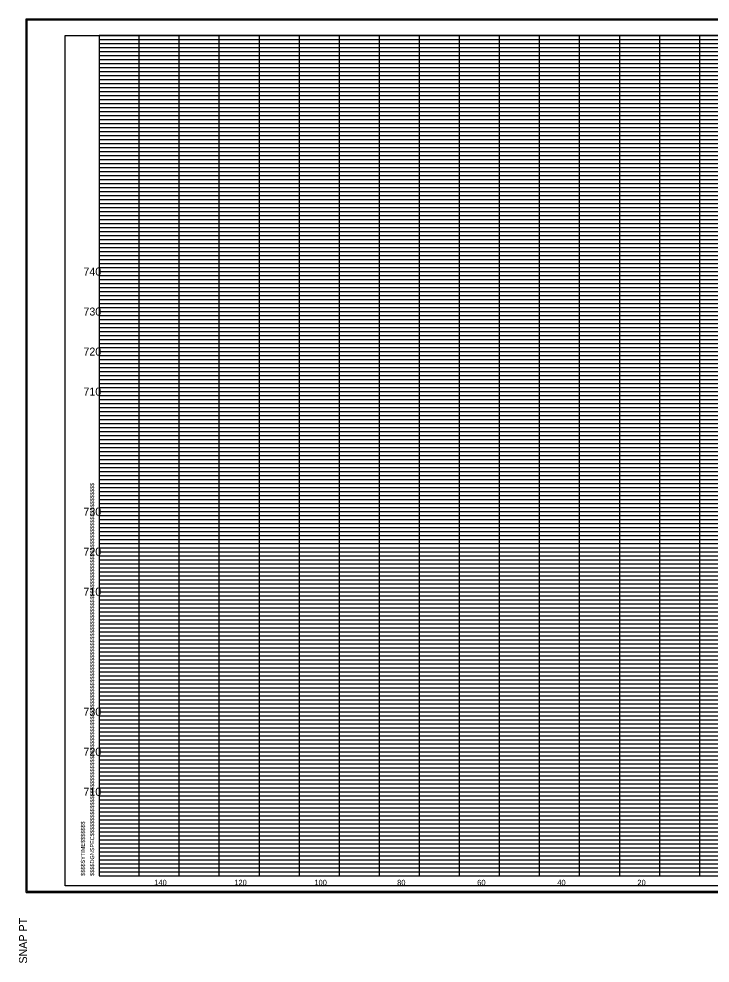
# Model space of a CAD drawing. Extents: x -200 to 1704, y -325 to 2307.
# Drawn here: x 979.9 to 1152.6, y 1248.2 to 1484.1 of the extents above; entities that cross this region are included whole.
import ezdxf

# ---------------------------------------------------------------- set-up
doc = ezdxf.new("R2010")
doc.units = 0
for name, color, linetype in [('DESIGN - SHEET - Corner Text', 7, 'Continuous'), ('DESIGN - SHEET - Light Grid', 7, 'Continuous'), ('DESIGN - SHEET - Linework', 7, 'Continuous'), ('DESIGN - SHEET - Plot Shape', 7, 'Continuous'), ('DESIGN - TYPICAL - Text', 7, 'Continuous')]:
    doc.layers.add(name, color=color, linetype=linetype)

msp = doc.modelspace()

# ---------------------------------------------------------------- linework, layer by layer
at = {"layer": 'DESIGN - SHEET - Light Grid'}
for p, q in [((1000, 1479), (1080, 1479)), ((1000, 1478), (1080, 1478)), ((1080, 1479), (1160, 1479)), ((1080, 1478), (1160, 1478)), ((1000, 1477), (1080, 1477)), ((1000, 1476), (1080, 1476)), ((1000, 1475), (1080, 1475)), ((1080, 1477), (1160, 1477)), ((1080, 1476), (1160, 1476)), ((1080, 1475), (1160, 1475)), ((1000, 1474), (1080, 1474)), ((1000, 1473), (1080, 1473)), ((1080, 1474), (1160, 1474)), ((1080, 1473), (1160, 1473)), ((1000, 1472), (1080, 1472)), ((1000, 1471), (1080, 1471)), ((1080, 1472), (1160, 1472)), ((1080, 1471), (1160, 1471)), ((1000, 1469), (1080, 1469)), ((1000, 1468), (1080, 1468)), ((1080, 1469), (1160, 1469)), ((1080, 1468), (1160, 1468)), ((1000, 1467), (1080, 1467)), ((1000, 1466), (1080, 1466)), ((1080, 1467), (1160, 1467)), ((1080, 1466), (1160, 1466)), ((1000, 1465), (1080, 1465)), ((1000, 1464), (1080, 1464)), ((1000, 1463), (1080, 1463)), ((1080, 1465), (1160, 1465)), ((1080, 1464), (1160, 1464)), ((1080, 1463), (1160, 1463)), ((1000, 1462), (1080, 1462)), ((1000, 1461), (1080, 1461)), ((1080, 1462), (1160, 1462)), ((1080, 1461), (1160, 1461)), ((1000, 1459), (1080, 1459)), ((1080, 1459), (1160, 1459)), ((1000, 1458), (1080, 1458)), ((1000, 1457), (1080, 1457)), ((1000, 1456), (1080, 1456)), ((1080, 1458), (1160, 1458)), ((1080, 1457), (1160, 1457)), ((1080, 1456), (1160, 1456)), ((1000, 1455), (1080, 1455)), ((1000, 1454), (1080, 1454)), ((1080, 1455), (1160, 1455)), ((1080, 1454), (1160, 1454)), ((1000, 1453), (1080, 1453)), ((1000, 1452), (1080, 1452)), ((1080, 1453), (1160, 1453)), ((1080, 1452), (1160, 1452)), ((1000, 1451), (1080, 1451)), ((1000, 1449), (1080, 1449)), ((1080, 1451), (1160, 1451)), ((1080, 1449), (1160, 1449)), ((1000, 1448), (1080, 1448)), ((1000, 1447), (1080, 1447)), ((1080, 1448), (1160, 1448)), ((1080, 1447), (1160, 1447)), ((1000, 1446), (1080, 1446)), ((1000, 1445), (1080, 1445)), ((1080, 1446), (1160, 1446)), ((1080, 1445), (1160, 1445)), ((1000, 1444), (1080, 1444)), ((1000, 1443), (1080, 1443)), ((1000, 1442), (1080, 1442)), ((1080, 1444), (1160, 1444)), ((1080, 1443), (1160, 1443)), ((1080, 1442), (1160, 1442)), ((1000, 1441), (1080, 1441)), ((1080, 1441), (1160, 1441)), ((1000, 1439), (1080, 1439)), ((1000, 1438), (1080, 1438)), ((1000, 1437), (1080, 1437)), ((1080, 1439), (1160, 1439)), ((1080, 1438), (1160, 1438)), ((1080, 1437), (1160, 1437)), ((1000, 1436), (1080, 1436)), ((1000, 1435), (1080, 1435)), ((1080, 1436), (1160, 1436)), ((1080, 1435), (1160, 1435)), ((1000, 1434), (1080, 1434)), ((1000, 1433), (1080, 1433)), ((1080, 1434), (1160, 1434)), ((1080, 1433), (1160, 1433)), ((1000, 1432), (1080, 1432)), ((1000, 1431), (1080, 1431)), ((1080, 1432), (1160, 1432)), ((1080, 1431), (1160, 1431)), ((1000, 1429), (1080, 1429)), ((1000, 1428), (1080, 1428)), ((1080, 1429), (1160, 1429)), ((1080, 1428), (1160, 1428)), ((1000, 1427), (1080, 1427)), ((1000, 1426), (1080, 1426)), ((1080, 1427), (1160, 1427)), ((1080, 1426), (1160, 1426)), ((1000, 1425), (1080, 1425)), ((1000, 1424), (1080, 1424)), ((1000, 1423), (1080, 1423)), ((1080, 1425), (1160, 1425)), ((1080, 1424), (1160, 1424)), ((1080, 1423), (1160, 1423)), ((1000, 1422), (1080, 1422)), ((1000, 1421), (1080, 1421)), ((1080, 1422), (1160, 1422)), ((1080, 1421), (1160, 1421)), ((1000, 1419), (1080, 1419)), ((1080, 1419), (1160, 1419)), ((1000, 1418), (1080, 1418)), ((1000, 1417), (1080, 1417)), ((1000, 1416), (1080, 1416)), ((1080, 1418), (1160, 1418)), ((1080, 1417), (1160, 1417)), ((1080, 1416), (1160, 1416)), ((1000, 1415), (1080, 1415)), ((1000, 1414), (1080, 1414)), ((1080, 1415), (1160, 1415)), ((1080, 1414), (1160, 1414)), ((1000, 1413), (1080, 1413)), ((1000, 1412), (1080, 1412)), ((1080, 1413), (1160, 1413)), ((1080, 1412), (1160, 1412)), ((1000, 1411), (1080, 1411)), ((1000, 1409), (1080, 1409)), ((1080, 1411), (1160, 1411)), ((1080, 1409), (1160, 1409)), ((1000, 1408), (1080, 1408)), ((1000, 1407), (1080, 1407)), ((1080, 1408), (1160, 1408)), ((1080, 1407), (1160, 1407)), ((1000, 1406), (1080, 1406)), ((1000, 1405), (1080, 1405)), ((1000, 1404), (1080, 1404)), ((1080, 1406), (1160, 1406)), ((1080, 1405), (1160, 1405)), ((1080, 1404), (1160, 1404)), ((1000, 1403), (1080, 1403)), ((1000, 1402), (1080, 1402)), ((1080, 1403), (1160, 1403)), ((1080, 1402), (1160, 1402)), ((1000, 1401), (1080, 1401)), ((1080, 1401), (1160, 1401)), ((1000, 1399), (1080, 1399)), ((1000, 1398), (1080, 1398)), ((1000, 1397), (1080, 1397)), ((1080, 1399), (1160, 1399)), ((1080, 1398), (1160, 1398)), ((1080, 1397), (1160, 1397)), ((1000, 1396), (1080, 1396)), ((1000, 1395), (1080, 1395)), ((1080, 1396), (1160, 1396)), ((1080, 1395), (1160, 1395)), ((1000, 1394), (1080, 1394)), ((1000, 1393), (1080, 1393)), ((1080, 1394), (1160, 1394)), ((1080, 1393), (1160, 1393)), ((1000, 1392), (1080, 1392)), ((1000, 1391), (1080, 1391)), ((1080, 1392), (1160, 1392)), ((1080, 1391), (1160, 1391)), ((1000, 1389), (1080, 1389)), ((1000, 1388), (1080, 1388)), ((1080, 1389), (1160, 1389)), ((1080, 1388), (1160, 1388)), ((1000, 1387), (1080, 1387)), ((1000, 1386), (1080, 1386)), ((1080, 1387), (1160, 1387)), ((1080, 1386), (1160, 1386)), ((1000, 1385), (1080, 1385)), ((1000, 1384), (1080, 1384)), ((1000, 1383), (1080, 1383)), ((1080, 1385), (1160, 1385)), ((1080, 1384), (1160, 1384)), ((1080, 1383), (1160, 1383)), ((1000, 1382), (1080, 1382)), ((1000, 1381), (1080, 1381)), ((1080, 1382), (1160, 1382)), ((1080, 1381), (1160, 1381)), ((1000, 1379), (1080, 1379)), ((1000, 1378), (1080, 1378)), ((1080, 1379), (1160, 1379)), ((1080, 1378), (1160, 1378)), ((1000, 1377), (1080, 1377)), ((1000, 1376), (1080, 1376)), ((1080, 1377), (1160, 1377)), ((1080, 1376), (1160, 1376)), ((1000, 1375), (1080, 1375)), ((1000, 1374), (1080, 1374)), ((1080, 1375), (1160, 1375)), ((1080, 1374), (1160, 1374)), ((1000, 1373), (1080, 1373)), ((1000, 1372), (1080, 1372)), ((1000, 1371), (1080, 1371)), ((1080, 1373), (1160, 1373)), ((1080, 1372), (1160, 1372)), ((1080, 1371), (1160, 1371)), ((1000, 1369), (1080, 1369)), ((1080, 1369), (1160, 1369)), ((1000, 1368), (1080, 1368)), ((1000, 1367), (1080, 1367)), ((1080, 1368), (1160, 1368)), ((1080, 1367), (1160, 1367)), ((1000, 1366), (1080, 1366)), ((1000, 1365), (1080, 1365)), ((1000, 1364), (1080, 1364)), ((1080, 1366), (1160, 1366)), ((1080, 1365), (1160, 1365)), ((1080, 1364), (1160, 1364)), ((1000, 1363), (1080, 1363)), ((1000, 1362), (1080, 1362)), ((1080, 1363), (1160, 1363)), ((1080, 1362), (1160, 1362)), ((1000, 1361), (1080, 1361)), ((1080, 1361), (1160, 1361)), ((1000, 1359), (1080, 1359)), ((1000, 1358), (1080, 1358)), ((1000, 1357), (1080, 1357)), ((1080, 1359), (1160, 1359)), ((1080, 1358), (1160, 1358)), ((1080, 1357), (1160, 1357)), ((1000, 1356), (1080, 1356)), ((1000, 1355), (1080, 1355)), ((1080, 1356), (1160, 1356)), ((1080, 1355), (1160, 1355)), ((1000, 1354), (1080, 1354)), ((1000, 1353), (1080, 1353)), ((1080, 1354), (1160, 1354)), ((1080, 1353), (1160, 1353)), ((1000, 1352), (1080, 1352)), ((1000, 1351), (1080, 1351)), ((1080, 1352), (1160, 1352)), ((1080, 1351), (1160, 1351)), ((1000, 1349), (1080, 1349)), ((1000, 1348), (1080, 1348)), ((1080, 1349), (1160, 1349)), ((1080, 1348), (1160, 1348)), ((1000, 1347), (1080, 1347)), ((1000, 1346), (1080, 1346)), ((1000, 1345), (1080, 1345)), ((1080, 1347), (1160, 1347)), ((1080, 1346), (1160, 1346)), ((1080, 1345), (1160, 1345)), ((1000, 1344), (1080, 1344)), ((1000, 1343), (1080, 1343)), ((1080, 1344), (1160, 1344)), ((1080, 1343), (1160, 1343)), ((1000, 1342), (1080, 1342)), ((1000, 1341), (1080, 1341)), ((1080, 1342), (1160, 1342)), ((1080, 1341), (1160, 1341)), ((1000, 1339), (1080, 1339)), ((1000, 1338), (1080, 1338)), ((1080, 1339), (1160, 1339)), ((1080, 1338), (1160, 1338)), ((1000, 1337), (1080, 1337)), ((1000, 1336), (1080, 1336)), ((1080, 1337), (1160, 1337)), ((1080, 1336), (1160, 1336)), ((1000, 1335), (1080, 1335)), ((1000, 1334), (1080, 1334)), ((1080, 1335), (1160, 1335)), ((1080, 1334), (1160, 1334)), ((1000, 1333), (1080, 1333)), ((1000, 1332), (1080, 1332)), ((1000, 1331), (1080, 1331)), ((1080, 1333), (1160, 1333)), ((1080, 1332), (1160, 1332)), ((1080, 1331), (1160, 1331)), ((1000, 1329), (1080, 1329)), ((1080, 1329), (1160, 1329)), ((1000, 1328), (1080, 1328)), ((1000, 1327), (1080, 1327)), ((1080, 1328), (1160, 1328)), ((1080, 1327), (1160, 1327)), ((1000, 1326), (1080, 1326)), ((1000, 1325), (1080, 1325)), ((1000, 1324), (1080, 1324)), ((1080, 1326), (1160, 1326)), ((1080, 1325), (1160, 1325)), ((1080, 1324), (1160, 1324)), ((1000, 1323), (1080, 1323)), ((1000, 1322), (1080, 1322)), ((1080, 1323), (1160, 1323)), ((1080, 1322), (1160, 1322)), ((1000, 1321), (1080, 1321)), ((1080, 1321), (1160, 1321)), ((1000, 1319), (1080, 1319)), ((1000, 1318), (1080, 1318)), ((1000, 1317), (1080, 1317)), ((1080, 1319), (1160, 1319)), ((1080, 1318), (1160, 1318)), ((1080, 1317), (1160, 1317)), ((1000, 1316), (1080, 1316)), ((1000, 1315), (1080, 1315)), ((1080, 1316), (1160, 1316)), ((1080, 1315), (1160, 1315)), ((1000, 1314), (1080, 1314)), ((1000, 1313), (1080, 1313)), ((1000, 1312), (1080, 1312)), ((1080, 1314), (1160, 1314)), ((1080, 1313), (1160, 1313)), ((1080, 1312), (1160, 1312)), ((1000, 1311), (1080, 1311)), ((1080, 1311), (1160, 1311)), ((1000, 1309), (1080, 1309)), ((1000, 1308), (1080, 1308)), ((1080, 1309), (1160, 1309)), ((1080, 1308), (1160, 1308)), ((1000, 1307), (1080, 1307)), ((1000, 1306), (1080, 1306)), ((1000, 1305), (1080, 1305)), ((1080, 1307), (1160, 1307)), ((1080, 1306), (1160, 1306)), ((1080, 1305), (1160, 1305)), ((1000, 1304), (1080, 1304)), ((1000, 1303), (1080, 1303)), ((1080, 1304), (1160, 1304)), ((1080, 1303), (1160, 1303)), ((1000, 1302), (1080, 1302)), ((1000, 1301), (1080, 1301)), ((1080, 1302), (1160, 1302)), ((1080, 1301), (1160, 1301)), ((1000, 1299), (1080, 1299)), ((1000, 1298), (1080, 1298)), ((1080, 1299), (1160, 1299)), ((1080, 1298), (1160, 1298)), ((1000, 1297), (1080, 1297)), ((1000, 1296), (1080, 1296)), ((1080, 1297), (1160, 1297)), ((1080, 1296), (1160, 1296)), ((1000, 1295), (1080, 1295)), ((1000, 1294), (1080, 1294)), ((1080, 1295), (1160, 1295)), ((1080, 1294), (1160, 1294)), ((1000, 1293), (1080, 1293)), ((1000, 1292), (1080, 1292)), ((1000, 1291), (1080, 1291)), ((1080, 1293), (1160, 1293)), ((1080, 1292), (1160, 1292)), ((1080, 1291), (1160, 1291)), ((1000, 1289), (1080, 1289)), ((1080, 1289), (1160, 1289)), ((1000, 1288), (1080, 1288)), ((1000, 1287), (1080, 1287)), ((1000, 1286), (1080, 1286)), ((1080, 1288), (1160, 1288)), ((1080, 1287), (1160, 1287)), ((1080, 1286), (1160, 1286)), ((1000, 1285), (1080, 1285)), ((1000, 1284), (1080, 1284)), ((1080, 1285), (1160, 1285)), ((1080, 1284), (1160, 1284)), ((1000, 1283), (1080, 1283)), ((1000, 1282), (1080, 1282)), ((1080, 1283), (1160, 1283)), ((1080, 1282), (1160, 1282)), ((1000, 1281), (1080, 1281)), ((1000, 1279), (1080, 1279)), ((1080, 1281), (1160, 1281)), ((1080, 1279), (1160, 1279)), ((1000, 1278), (1080, 1278)), ((1000, 1277), (1080, 1277)), ((1080, 1278), (1160, 1278)), ((1080, 1277), (1160, 1277)), ((1000, 1276), (1080, 1276)), ((1000, 1275), (1080, 1275)), ((1080, 1276), (1160, 1276)), ((1080, 1275), (1160, 1275)), ((1000, 1274), (1080, 1274)), ((1000, 1273), (1080, 1273)), ((1000, 1272), (1080, 1272)), ((1080, 1274), (1160, 1274)), ((1080, 1273), (1160, 1273)), ((1080, 1272), (1160, 1272)), ((1000, 1271), (1080, 1271)), ((1080, 1271), (1160, 1271))]:
    msp.add_line(p, q, dxfattribs=at)
at = {"layer": 'DESIGN - SHEET - Linework'}
for p, q in [((981.77, 1265.86), (981.77, 1484.14)), ((981.77, 1484.14), (1322.17, 1484.14)), ((1010, 1270), (1010, 1480)), ((1020, 1270), (1020, 1480)), ((1030, 1270), (1030, 1480)), ((1040, 1270), (1040, 1480)), ((1050, 1270), (1050, 1480)), ((1060, 1270), (1060, 1480)), ((1070, 1270), (1070, 1480)), ((1080, 1270), (1080, 1480)), ((1090, 1270), (1090, 1480)), ((1100, 1270), (1100, 1480)), ((1110, 1270), (1110, 1480)), ((1120, 1270), (1120, 1480)), ((1130, 1270), (1130, 1480)), ((1140, 1270), (1140, 1480)), ((1150, 1270), (1150, 1480)), ((1000, 1470), (1280, 1470)), ((1000, 1460), (1320, 1460)), ((1000, 1450), (1320, 1450)), ((1000, 1440), (1320, 1440)), ((1000, 1430), (1320, 1430)), ((1000, 1420), (1320, 1420)), ((1000, 1410), (1320, 1410)), ((1000, 1400), (1320, 1400)), ((1000, 1390), (1320, 1390)), ((1000, 1380), (1320, 1380)), ((1000, 1370), (1320, 1370)), ((1000, 1360), (1320, 1360)), ((1000, 1350), (1320, 1350)), ((1000, 1340), (1320, 1340)), ((1000, 1330), (1320, 1330)), ((1000, 1320), (1320, 1320)), ((1000, 1310), (1320, 1310)), ((1000, 1300), (1320, 1300)), ((1000, 1290), (1320, 1290)), ((1000, 1280), (1320, 1280)), ((981.77, 1265.86), (1322.17, 1265.86))]:
    msp.add_line(p, q, dxfattribs=at)
msp.add_lwpolyline([(1000, 1480), (1000, 1270), (1320, 1270), (1320, 1480), (1000, 1480)], dxfattribs=at)
at = {"layer": 'DESIGN - SHEET - Plot Shape'}
for points in [[(981.97, 1483.94), (1321.97, 1483.94), (1321.97, 1266.06), (981.97, 1266.06)], [(991.5, 1480), (1320, 1480), (1320, 1267.5), (991.5, 1267.5)]]:
    msp.add_lwpolyline(points, close=True, dxfattribs=at)

# ---------------------------------------------------------------- texts
at = {"layer": 'DESIGN - SHEET - Corner Text'}
for s, height, p in [('$$$$DGNSPEC$$$$$$$$$$$$$$$$$$$$$$$$$$$$$$$$$$$$$$$$$$$$$$$$$$$$$$$$$$$$$$$$$$$$$$$$$$$$$$$$$$$$$$$$$$$$$$$$$$$$$$$$$$$$$$$$$$$', 1.00002, (998.74, 1270)), ('$$$$SYTIME$$$$$$$', 1, (996.42, 1270)), ('SNAP PT  ', 2, (981.97, 1248.06))]:
    msp.add_text(s, height=height, rotation=90, dxfattribs=at).set_placement(p)
at = {"layer": 'DESIGN - TYPICAL - Text'}
for s, height, p in [('     740     ', 2, (992.34, 1420)), ('     730     ', 2, (992.34, 1410)), ('     720     ', 2, (992.34, 1400)), ('     710     ', 2, (992.34, 1390)), ('     730     ', 2, (992.34, 1360)), ('     720     ', 2, (992.34, 1350)), ('     710     ', 2, (992.34, 1340)), ('     730     ', 2, (992.34, 1310)), ('     720     ', 2, (992.34, 1300)), ('     710     ', 2, (992.34, 1290)), ('     140     ', 1.4, (1011.14, 1267.6)), ('     120     ', 1.4, (1031.14, 1267.6)), ('     100     ', 1.4, (1051.14, 1267.6)), ('     80     ', 1.4, (1071.82, 1267.6)), ('     60     ', 1.4, (1091.82, 1267.6)), ('     40     ', 1.4, (1111.82, 1267.6)), ('     20     ', 1.4, (1131.82, 1267.6))]:
    msp.add_text(s, height=height, dxfattribs=at).set_placement(p)

doc.saveas('drawing.dxf')
